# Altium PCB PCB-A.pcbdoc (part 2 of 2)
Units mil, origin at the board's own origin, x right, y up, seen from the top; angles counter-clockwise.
Board outline 6045 x 2702.2 mil, 4 copper layers (Top Layer, Inner1, Inner2, Bottom Layer); 82 components, 118 nets, 419 pads, 214 vias.
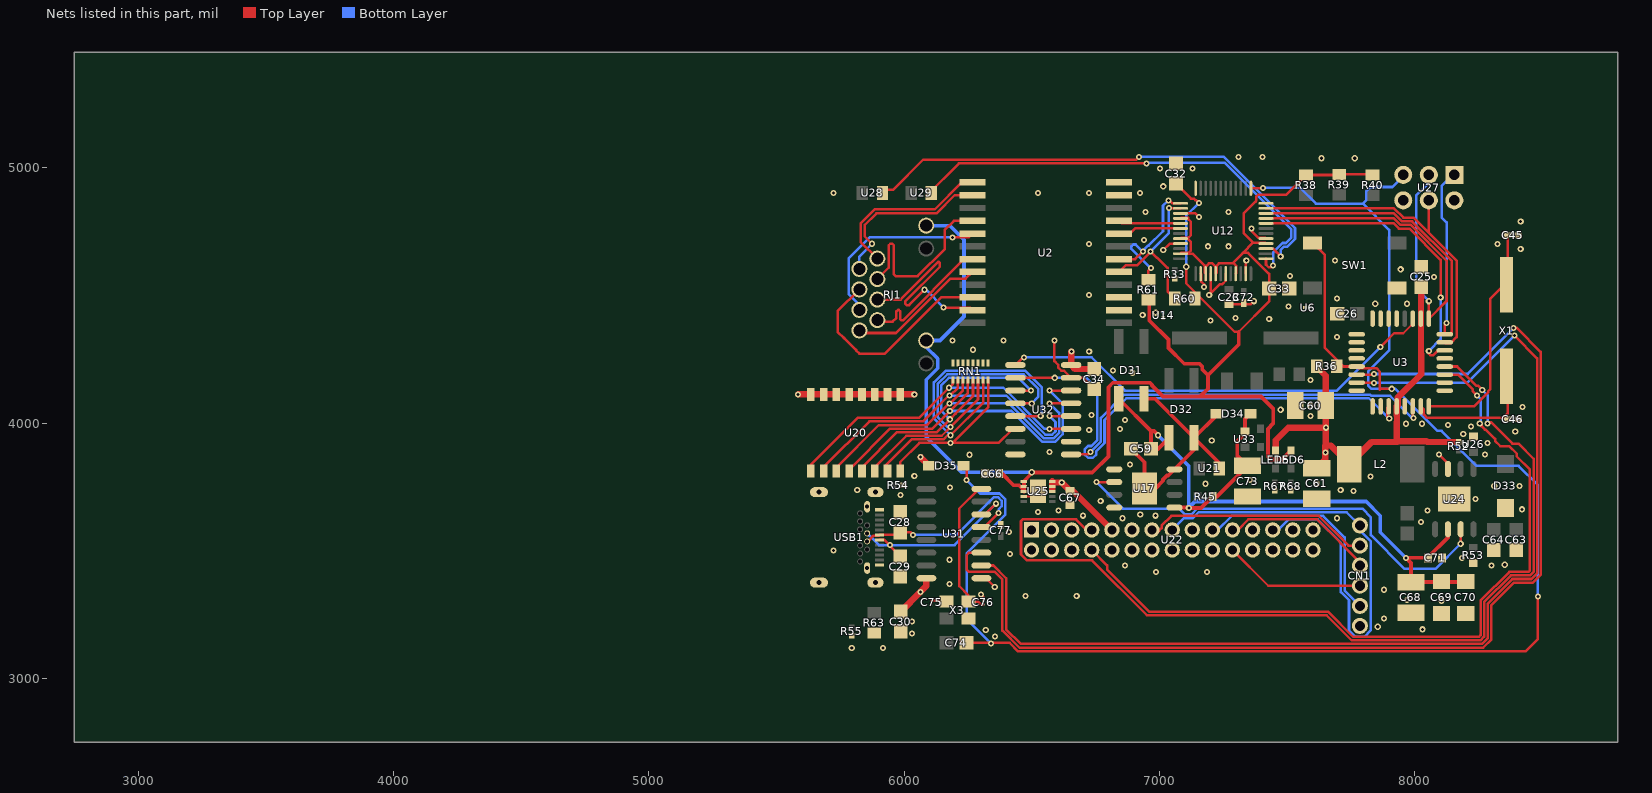
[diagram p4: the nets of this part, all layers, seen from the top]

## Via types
v1: diameter 24, hole 12, Top Layer to Bottom Layer, 173 vias
v2: diameter 24.02, hole 12.01, Top Layer to Bottom Layer, 41 vias

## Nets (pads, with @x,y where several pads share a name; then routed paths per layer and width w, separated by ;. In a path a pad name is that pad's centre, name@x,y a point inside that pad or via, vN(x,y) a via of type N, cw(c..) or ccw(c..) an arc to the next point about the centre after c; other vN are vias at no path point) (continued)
$9N13153: C76.2 U31.8 X3.3 | length 560.3
  Top Layer w10: U31.8@6302.7,3742.2 6293.44,3742.2 6216,3664.77 6216,3361.41 6252.15,3325.25 X3.3@6252.15,3300.65 6290.22,3300.65 6301.11,3289.76 6309.77,3289.76 C76.2@6310,3289.54
+5V: C25.1 C30.1 C34.2 C60.2 C61.2 C67.2 D35.1 L2.2 LED5.2 R36.1 R52.2 U3.4 U3.18 U20.9 U20.10 U20.11 U20.12 U20.13 U20.14 U20.15 U20.16 U22.9 U25.8 U25.9 U25.10 U27.2 U31.16 U32.16 | length 3087.4
  Top Layer w25: v1(5585,4112.2) U20.16@5635,4112.2 U20.15@5685,4112.2 U20.14@5735,4112.2 U20.13@5785,4112.2 U20.12@5835,4112.2 U20.11@5885,4112.2 U20.10@5935,4112.2 U20.9@5985,4112.2 v1(6040,4112.2) ; C30.1@5987.65,3261.99 v1(6064.48,3338.82) 6087.3,3361.64 U31.16@6087.3,3392.2 ; v1(6065,3867.2) 6065,3865.27 D35.1@6098.07,3832.2 ; 6580.57,3742.2 U25.9@6580.57,3751.88 U25.10@6580.57,3771.57 ; U25.10@6585,3767.2 v1(6617.56,3767.2) C67.2@6650,3734.76 6660.59,3734.76 U22.9@6813.78,3581.57 ; v1(6655,4280.2) 6655,4228.18 U32.16@6654.02,4227.2 6669.65,4211.57 C34.2@6745,4211.57 ; LED5.2@7455,3892.63 7455,3932.2 7504.62,3981.82 v1(7652.09,3981.82) ; R36.1@7615.63,4222.2 7652.09,4185.75 C60.2@7652.09,4068.58 v1(7652.09,3981.82) ; C61.2@7616.27,3823.32 7650,3857.05 v1(7650,3884.94) 7650,3912.2 ; C25.1@8025,4532.83 8025,4490.35 8024.49,4489.84 8024.49,4269.57 8025,4269.06 8025,4191.77 7933.39,4100.16 7933.39,4069.34 U3.4@7929.25,4065.2 7929.25,4031.1 7930.51,4029.84 7930.51,4004.57 7929.25,4003.31 7929.25,3927.96 7931.6,3925.62 ; R52.2@8172.16,3925.62 8049.31,3925.62 8045.83,3929.09 7935.07,3929.09 7931.6,3925.62 ; 7650,3912.2 7671.28,3912.2 L2.2@7744.15,3839.33 7830.43,3925.62 7931.6,3925.62 ; 7650,3912.2 7652.09,3914.29 v1(7652.09,3981.82)
+33V: C32.1 C33.1 C66.2 LED6.2 R38.2 R39.2 R40.2 R60.2 R61.2 RJ1.9 RJ1.11 U12.4 U12.8 U12.11 U12.15 U12.17 U12.21 U12.28 U25.1 U25.2 U25.3 | length 6746.3
  Top Layer w10: C32.1@7065,4937.83 7123.56,4879.28 7134.72,4879.28 7141.79,4872.2 7145,4872.2 v2(7155,4862.2) ; U12.8@7082.68,4722.67 7086.07,4726.07 7113.64,4726.07 ; U12.4@7082.68,4801.41 7086.07,4804.81 7113.64,4804.81 7113.64,4798.03 7123.19,4788.49 7123.19,4735.61 7113.64,4726.07 ; v2(7105,4612.2) 7105,4547.2 7294.68,4357.52 7310.61,4357.52 7429.88,4476.79 C33.1@7429.88,4526.84 7429.88,4584.09 7347.79,4666.18 7327.07,4666.18 ; U12.15@7181.1,4584.88 7177.72,4588.27 7177.72,4615.85 ; U12.21@7299.21,4584.88 7300.83,4586.5 7300.83,4615.85 7291.28,4625.4 7286.28,4625.4 ; 7376.79,4867.21 7330,4820.42 7330,4743.64 7367.26,4706.38 ; 7380,4870.42 7380,4887.2 7387.07,4894.28 7497.07,4894.28 R38.2@7574.25,4971.46 7702.14,4971.46 R39.2@7704.25,4973.56 7833.02,4973.56 R40.2@7835,4971.57 ; U12.28@7417.32,4702.99 7413.94,4706.38 7367.26,4706.38 ; 7113.64,4726.07 7113.64,4719.29 7123.19,4709.75 7123.19,4676.55 7113.64,4667.01 7086.06,4667.01 U12.11@7082.68,4663.62 7129.94,4663.62 7177.72,4615.85 ; 7177.72,4615.85 7184.49,4615.85 7194.04,4625.4 7207.54,4625.4 7220.47,4612.47 U12.17@7220.47,4584.88 7223.86,4588.28 7223.86,4615.85 7233.41,4625.4 7286.28,4625.4 ; 7286.28,4625.4 7327.07,4666.18 ; 7327.07,4666.18 7367.26,4706.38
  Top Layer w15: C66.2@6372.56,3802.2 6383.22,3802.2 6429.11,3756.31 6450.32,3756.31 U25.3@6469.43,3737.2 ; U25.3@6469.43,3732.2 U25.3@6469.43,3737.2 ; R61.2@6956.59,4482.39 6960,4478.99 6960,4402.2 7035.17,4327.03 7035.17,4294.36 7097.33,4232.2 7156.58,4232.2 7167.49,4221.29 7167.49,4209.71 7190,4187.2 ; 7310.61,4357.52 7310.61,4307.81 7190,4187.2 ; LED6.2@7515,3892.63 7479.57,3857.2 7435.61,3857.2 7425,3867.81 7425,3977.2 7445.5,3997.7 7445.5,4056.7 7398.24,4103.97 7159.59,4103.97 ; U25.3@6469.43,3737.2 U25.2@6469.43,3751.88 U25.1@6469.43,3771.57 6480.4,3782.54 6480.4,3784.06 6502.05,3805.7 6736.79,3805.7 6800,3868.92 6800,4140.43 6817.27,4157.71 6962.73,4157.71 6970.63,4149.8 6970.63,4147.47 7014.14,4103.97 7159.59,4103.97 ; 7159.59,4103.97 7190,4134.38 7190,4187.2
  Bottom Layer w10: v2(7105,4612.2) 7105,4812.2 v2(7155,4862.2)
  Bottom Layer w15: RJ1.9@6086.77,4772.88 6180,4772.87 6235,4717.87 6235,4417.2 6141.07,4323.27 RJ1.11@6086.77,4323.27 6086.76,4297.14 6131.76,4252.14 6131.76,4214.87 6086.76,4169.87 6086.76,3945.44 6225,3807.2 v1(6500,3807.2)
A0: U3.23
A1: U3.24
A2: U3.25
A3: U3.26
A4: U3.27
A5: U3.28
A6: U3.19 U32.1 | length 1751.2
  Top Layer w10: U32.1@6435.98,4227.2 6465.98,4257.2 v1(6470,4257.2) ; v1(7865,4297.2) 7919.54,4351.74 7954.99,4351.74 7992.24,4388.99 U3.19@7992.24,4409.2
  Bottom Layer w10: v1(6470,4257.2) 6735,4257.2 6865,4127.2 7695,4127.2 v1(7865,4297.2)
A7: U3.22
ACTLED: U12.27 U28.1 | length 1998.2
  Top Layer w10: U28.1@5915.5,4913.35 5956.35,4913.35 6074.2,5031.2 6909,5031.2 v2(6920,5042.2) ; U12.27@7417.32,4683.3 7444.93,4683.3 7457.85,4670.38 7457.85,4669.36 v1(7475,4652.2)
  Bottom Layer w10: v2(6920,5042.2) 6921.07,5043.27 7251.07,5043.27 7531.01,4763.33 7531.01,4721.08 7501.13,4691.2 7488.43,4691.2 7475,4677.76 v1(7475,4652.2)
AGND: C23.1 C25.2 C26.1 C28.1 C29.1 C30.2 C32.2 C33.2 C34.1 C45.2 C46.1 C60.1 C61.1 C63.1 C64.1 C66.1 C67.1 C68.1 C69.1 C70.1 C71.1 C72.1 C73.1 C75.1 C76.1 C77.1 CN1.1 D33.2 R33.1 R53.1 R54.2 R55.2 R63.2 R67.1 R68.1 RN1.1 RN1.2 RN1.3 RN1.4 RN1.5 RN1.6 RN1.7 RN1.8 SW1.1 U3.5 U3.21 U6.1 U12.3 U12.9 U12.14 U12.16 U12.19 U12.23 U12.29 U12.48 U14.1 U17.5 U17.8 U22.10 U22.16 U22.26 U24.7 U24.9 U25.4 U25.11 U26.1 U27.6 U31.1 U32.8 U32.10 U32.15 USB1.25 USB1.26 USB1.27 USB1.28 USB1.A1 USB1.A12 USB1.B1 USB1.B12 X3.2 X3.4 | length 1217.2
  Top Layer w10: C75.1@6107.61,3304.9 6161.29,3304.9 X3.4@6165.53,3300.65 ; v1(6301.73,3327.95) 6310,3319.68 C76.1@6310,3304.9 ; U31.1@6302.7,3392.2 6320,3392.2 v1(6355,3357.2) ; U25.4@6469.43,3712.51 6505.31,3712.51 U25.11@6525,3732.2 ; v1(6588.95,4322.85) 6588.95,4242.27 6602.9,4228.32 6602.9,4217.97 6615.96,4204.91 6626.32,4204.91 U32.15@6654.02,4177.2 6700.63,4177.2 C34.1@6745,4132.83 ; v1(7015,4677.2) 7040.79,4702.99 U12.9@7082.68,4702.99 ; U12.3@7082.68,4821.1 7141.1,4821.1 v1(7155,4807.2) ; U12.14@7161.42,4584.88 7163.72,4582.59 7163.72,4554.98 7175,4543.7 v1(7175,4532.2) ; v1(7195,4502.2) v1@7200.79,4507.99 ; U12.16@7200.79,4584.88 v1@7200.79,4507.99 ; U12.19@7259.84,4584.88 7259.84,4557.28 7246.92,4544.36 7237.15,4544.36 v1@7200.79,4507.99 ; C23.1@7272.81,4465.49 7358.29,4465.49 v1(7370,4477.2) ; U12.23@7338.58,4584.88 7338.58,4635.17 v1(7340.31,4636.9) ; v1(7360,4762.2) 7360,4752.4 7386.35,4726.05 7413.94,4726.05 U12.29@7417.32,4722.67 ; v1(8095,3877.2) 8130,3842.2 U24.7@8130,3820.32
  other v1: 5795,3118.65 5916.78,3118.65 6355.78,3163.95 6031.03,3175.13 6319.72,3190.12 8030,3192.2 7855,3202.2 6031.03,3222.62 7879.27,3234.02 8105,3303.95 7970,3307.2 6476.06,3323.12 6676.06,3323.12 7880,3347.2 6178.19,3369.32 6986.5,3416.67 7186.5,3416.67 6865,3442.2 8300,3442.2 8352.48,3445.16 6178.19,3464.68 8185,3472.2 6415,3487.2 5724.1,3501.3 6410.08,3573.11 8025,3612.2 6855,3627.2 7695,3627.2 6700,3637.2 6985,3637.2 6925,3642.2 6525,3652.2 6605,3657.2 8050,3657.2 8420,3662.2 6770,3694.2 8238.47,3702.21 5985.4,3717.83 7759.95,3734.24 5816.55,3737.21 7710,3737.2 6180,3747.2 8311.13,3753.58 8410.16,3753.58 7180,3762.2 7616.27,3763.58 7355,3777.2 7826.62,3791.3 6040,3792.2 6884.7,3837.38 6256.45,3875.79 8275,3877.2 6570,3887.2 8285,3922.2 7205,3932.2 8190,3957.2 8393.57,3967.2 6725,3972.2 6845,3977.2 8220,3987.2 8130,3992.2 7965,3997.2 8028.57,3997.2 6865,4012.2 7592.35,4027.55 6734,4030.97 7475,4052.2 8421.36,4063.57 7592.35,4068.58 7592.35,4168.04 6894.15,4197.24 6818.76,4205.97 6725,4280.2 6270,4287.2 6188.95,4322.85 6388.95,4322.85 7695,4337.2 7200,4402.2 7430,4407.2 7298.56,4411.36 6934.5,4423.64 6985.5,4432.2 7505,4457.2 7845.37,4467.2 7970,4467.2 7695.91,4487.2 6724.1,4501.3 8075,4572.2 7511.67,4576.61 7945,4602.2 7687.72,4637.02 8415,4682.2 7190,4692.2 7270,4692.2 6724.1,4701.3 8324.1,4701.3 6940,4717.2 8415,4789.94 6945,4827.2 7270,4827.2 5724.1,4901.3 6524.1,4901.3 6724.1,4901.3 6924.1,4901.3 7015,4927.2 7002.1,4997.2 7130,4997.2 7635,5037.2 7765,5037.2 7310,5042.2 7404.09,5042.2
CAN_H: U22.1
CAN_H2: U22.3
CAN_L: U22.2
CAN_L2: U22.4
CDB: U17.6 U24.3 | length 1793
  Top Layer w10: v1(6753.76,3768.44) 6822.59,3768.44 U17.6@6823.09,3768.93 ; v1(8180,3527.2) U24.3@8180,3584.1
  Bottom Layer w10: v1(6753.76,3768.44) 6857,3665.2 7077,3665.2 7100,3642.2 7125.73,3642.2 7148.1,3664.57 7794.58,3664.57 7828.25,3630.9 7828.25,3561.43 7960.47,3429.2 8082,3429.2 v1(8180,3527.2)
D0: U3.30 U31.3 | length 4515.3
  Top Layer w10: U31.3@6302.7,3492.2 6255,3492.2 6245,3482.2 6245,3427.2 6255,3417.2 6355.2,3417.2 6385,3387.41 6385,3187.2 6452.2,3120 8267.8,3120 8300,3152.2 8300,3287.2 8388,3375.2 8463,3375.2 8493.2,3405.4 8493.2,4279 8400,4372.2 v2(8386.96,4372.2) ; U3.30@7772.5,4189.96 7837.76,4189.96 v2(7840,4192.2)
  Bottom Layer w10: v2(7840,4192.2) 8206.96,4192.2 v2(8386.96,4372.2)
D1: U3.31 U31.2 | length 4277.2
  Top Layer w10: U31.2@6302.7,3442.2 6350,3442.2 6400,3392.2 6400,3192 6457.15,3134.86 8262.85,3134.86 8286,3158 8286,3293 8382.2,3389.2 8457.2,3389.2 8479.2,3411.2 8479.2,4253 v2(8390,4342.2) ; U3.31@7772.5,4158.46 7773.76,4157.2 v2(7840,4157.2)
  Bottom Layer w10: v2(7840,4157.2) 8205,4157.2 v2(8390,4342.2)
D2: U3.32
D3: U3.1
D4: U3.2
D5: U3.9
D6: U3.10
D7: U3.11 U22.8 | length 3014.5
  Top Layer w10: U22.8@6735.04,3502.83 6795.04,3442.83 6795.04,3426.21 6960.04,3261.2 7660.8,3261.2 7759.15,3162.86 8251.26,3162.86 8258,3169.6 8258,3304.6 8370.6,3417.2 8445.6,3417.2 8451.2,3422.8 8451.2,3817.72 8399.46,3869.46 8399.46,3879.89 8369.73,3909.62 8334.92,3909.62 8314.44,3930.09 8314.44,3937.62 8277.44,3974.62 8274.92,3974.62 8261.44,3988.09 8261.44,3990.62 v1(8254.44,3997.62) ; U3.11@8117.5,4189.96 8168.96,4189.96 8227.66,4131.26 8227.66,4124.19 v2(8243.22,4108.62)
  Bottom Layer w10: v2(8243.22,4108.62) 8258.79,4093.06 8258.79,4001.96 v1(8254.44,3997.62)
D8: U3.12 U22.7 | length 3775.6
  Top Layer w10: U22.7@6735.04,3581.57 6714.28,3581.57 6673.28,3622.57 6464.26,3622.57 6457.82,3616.13 6457.82,3485.85 6481.84,3461.83 6736.13,3461.83 6950.76,3247.2 7655,3247.2 7753.35,3148.86 8257.06,3148.86 8272,3163.8 8272,3298.8 8376.4,3403.2 8451.4,3403.2 8465.2,3417 8465.2,3860.29 8406.21,3919.28 8382.93,3919.28 8300,4002.2 8289.03,4002.2 v1(8284.44,3997.62) ; U3.12@8117.5,4221.46 8165.75,4221.46 8241.81,4145.4 8248.88,4145.4 v2(8264.44,4129.84)
  Bottom Layer w10: v2(8264.44,4129.84) 8285.86,4108.42 8285.86,3999.03 v1(8284.44,3997.62)
D9: U3.13
DIR: U22.11
DN1: C29.2 U31.6 USB1.A7 USB1.B7 | length 773.8
  Top Layer w10: USB1.A7@5903.31,3542.36 5922.8,3542.36 v1@5945,3520.16 ; v1@5945,3518.71 5944.53,3518.25 C29.2@5985.4,3477.38 ; U31.6@6302.7,3642.2 6317.47,3642.2 v1(6359.45,3684.18)
  Bottom Layer w10: USB1.B7@5855.67,3567.96 5864.35,3559.27 5865.11,3559.27 5878.47,3545.9 5878.47,3545.14 5901.41,3522.2 v1(5945,3522.2) 6197.47,3522.2 v1(6359.45,3684.18)
DP1: C28.2 U31.5 USB1.A6 USB1.B6 | length 755.9
  Top Layer w10: USB1.B6@5855.67,3536.46 5858.22,3536.45 5881.04,3559.27 5900.54,3559.27 USB1.A6@5903.31,3562.04 5975.55,3562.04 C28.2@5985.4,3571.9 6025.31,3571.9 v1(6035,3562.2) ; U31.5@6302.7,3592.2 6315,3592.2 v1(6370,3647.2)
  Bottom Layer w10: v1(6035,3562.2) 6205,3562.2 6352.93,3710.13 6367.07,3710.13 6382.45,3694.75 6382.45,3674.66 6370,3662.2 v1(6370,3647.2)
ENCO_A: U22.17
ENCO_B: U22.18
ENCO_Z: U22.20
ETH1A: U2.2
ETH1B: U2.3
ETH2A: R60.1 U2.5 U12.2 | length 628.5
  Top Layer w10: U2.5@6842.4,4592.2 6868.74,4618.54 6913.85,4618.54 6965,4669.69 v2(6965,4672.2) 6990,4647.2 6992.24,4647.2 7032.07,4607.37 7032.07,4515.76 R60.1@7060.63,4487.2 ; v2(7037.07,4841.74) 7081.73,4841.74 U12.2@7082.68,4840.78
  Bottom Layer w10: v2(6965,4672.2) 7037.07,4744.28 v2(7037.07,4841.74)
ETH2B: R61.1 U2.6 U12.1 | length 627.5
  Top Layer w10: U2.6@6842.4,4642.2 6905,4642.2 v2(6935,4672.2) ; R61.1@6956.59,4561.13 6956.59,4597.2 v1(6966.59,4607.2) ; v2(7035,4872.2) 7037.93,4869.28 7042.07,4869.28 7050.87,4860.47 U12.1@7082.68,4860.47
  Bottom Layer w10: v1(6966.59,4607.2) 6965,4607.2 6890,4682.2 6890,4692.2 6897.07,4699.28 6907.07,4699.28 6934.14,4672.2 v2(6935,4672.2) 6941.99,4679.2 6941.99,4681.73 6955.47,4695.21 6958.01,4695.21 7014.06,4751.27 7014.06,4851.27 v2(7035,4872.2)
ETH3A: U2.8 U12.6 | length 248.6
  Top Layer w10: U2.8@6842.4,4742.2 6885,4742.2 6905,4762.2 7082.52,4762.2 U12.6@7082.68,4762.04
ETH3B: U2.9 U12.5 | length 244.6
  Top Layer w10: U2.9@6842.4,4792.2 6852.87,4781.73 U12.5@7082.68,4781.73
ETH4A: U2.11
ETH4B: U2.12
HALL_A: CN1.4 U22.21 | length 604.9
  Top Layer w10: U22.21@7286.22,3581.57 7306.98,3581.57 7347.98,3622.57 7618.16,3622.57 7792.08,3448.66 CN1.4@7785,3441.57
HALL_B: CN1.3 U22.22 | length 556.8
  Top Layer w10: U22.22@7286.22,3502.83 7426.22,3362.83 CN1.3@7785,3362.83
HALL_C: CN1.2 U22.19 | length 868.2
  Bottom Layer w10: U22.19@7207.48,3581.57 7228.24,3581.57 7283.24,3636.57 7640.63,3636.57 7725,3552.2 7725,3344.09 CN1.2@7785,3284.09
IP0: RN1.9 U20.1 U32.11 | length 1272.8
  Top Layer w10: U20.1@5635,3812.2 5635,3837.2 5818,4020.2 6057.92,4020.2 v1@6175.92,4138.2 ; v1(6176,4138.2) 6191.1,4153.3 RN1.9@6191.1,4169.41 ; v1(6570,3977.2) U32.11@6654.02,3977.2
  Bottom Layer w10: v1(6176,4138.2) 6389,4138.2 6550,3977.2 v1(6570,3977.2)
IP1: RN1.10 U20.2 U32.12 | length 1338.5
  Top Layer w10: U20.2@5685,3812.2 5685,3827.2 5864,4006.2 6073.92,4006.2 6174.97,4107.26 v1(6177.5,4107.26) 6180.05,4107.26 6210.79,4137.99 RN1.10@6210.79,4169.41 ; v1(6570,4027.2) U32.12@6654.02,4027.2
  Bottom Layer w10: v1(6177.5,4107.26) 6400.15,4107.26 6553.2,3954.2 6579.53,3954.2 6593,3967.68 6593,4004.2 v1(6570,4027.2)
IP2: RN1.11 U20.3 U32.13 | length 1386.1
  Top Layer w10: U20.3@5735,3812.2 5735,3826.35 5900.86,3992.2 6090,3992.2 6175.05,4077.26 v1(6177.5,4077.26) 6180.11,4077.26 6230.47,4127.62 RN1.11@6230.47,4169.41 ; v1(6570,4077.2) U32.13@6654.02,4077.2
  Bottom Layer w10: v1(6177.5,4077.26) 6410.35,4077.26 6547.4,3940.2 6585.33,3940.2 6607,3961.88 6607,4040.2 v1(6570,4077.2)
IP3: RN1.12 U20.4 U32.14 | length 1429
  Top Layer w10: U20.4@5785,3812.2 5786.82,3812.2 5790,3815.39 5790,3822.72 5945.48,3978.2 6110.49,3978.2 6156.01,4023.73 6156.01,4024.26 v1(6179.01,4047.26) 6180.11,4047.26 6250.16,4117.31 RN1.12@6250.16,4169.41 ; v1(6570,4127.2) U32.14@6654.02,4127.2
  Bottom Layer w10: v1(6179.01,4047.26) 6420.55,4047.26 6541.6,3926.2 6591.12,3926.2 6621,3956.08 6621,4076.2 v1(6570,4127.2)
IP4: RN1.13 U20.5 U32.3 | length 1222.5
  Top Layer w10: U20.5@5835,3812.2 5835,3826.35 5972.86,3964.2 6128.49,3964.2 v1(6179.01,4014.73) 6188.01,4023.73 6188.54,4023.73 6202.01,4037.2 6202.01,4037.73 6269.84,4105.56 RN1.13@6269.84,4169.41 ; U32.3@6435.98,4127.2 v1(6497.47,4127.2)
  Bottom Layer w10: v1(6179.01,4014.73) 6145,4048.74 6145,4147.2 6175,4177.2 6447.47,4177.2 v1(6497.47,4127.2)
IP5: RN1.14 U20.6 U32.4 | length 1367.9
  Top Layer w10: U20.6@5885,3812.2 5885,3826.35 6008.86,3950.2 6147.47,3950.2 v1(6182,3984.73) 6289.53,4092.26 RN1.14@6289.53,4169.41 ; U32.4@6435.98,4077.2 v1(6500,4077.2)
  Bottom Layer w10: v1(6182,3984.73) 6169.27,3984.73 6131,4023 6131,4153 6169.2,4191.2 6468.53,4191.2 6525,4134.73 6525,4102.2 v1(6500,4077.2)
IP6: RN1.15 U20.7 U32.5 | length 1513.7
  Top Layer w10: U20.7@5935,3812.2 5927.5,3819.7 5927.5,3833.85 6029.86,3936.2 6154.27,3936.2 6170.27,3952.2 v1(6182,3952.2) 6309.21,4079.41 RN1.15@6309.21,4169.41 ; U32.5@6435.98,4027.2 v1(6535,4027.2)
  Bottom Layer w10: v1(6182,3952.2) 6117,4017.2 6117,4158.8 6163.4,4205.2 6474.33,4205.2 6539,4140.53 6539,4031.2 v1(6535,4027.2)
IP7: RN1.16 U20.8 U32.6 | length 844.6
  Top Layer w10: U20.8@5985,3812.2 5985,3847.2 6060,3922.2 v1(6182,3922.2) v1@6190,3922.2 ; RN1.16@6328.9,4169.41 6328.9,4061.1 v1@6190,3922.2 ; U32.6@6435.98,3977.2 6425.63,3977.2 6370.63,3922.2 v1@6190,3922.2
LINKLED: U12.25 U29.1 | length 1834
  Top Layer w10: U29.1@6089.37,4892.2 6214.37,5017.2 v2(6950,5017.2) ; U12.25@7417.32,4643.93 7417.32,4620.74 7427.93,4610.13 7437.93,4610.13 v2(7445,4617.2)
  Bottom Layer w10: v2(6950,5017.2) 6952.01,5015.2 6952.01,5010.2 6962.01,5020.2 7254.34,5020.2 7517.01,4757.53 7517.01,4726.88 7495.33,4705.2 7482.63,4705.2 7445,4667.56 v2(7445,4617.2)
MISO: U3.16 U12.34 U27.1 | length 1768
  Top Layer w10: U12.34@7417.32,4821.1 7918.42,4821.1 7949.33,4790.2 7990,4790.2 8144.37,4635.83 8144.37,4356.57 8135.24,4347.44 U3.16@8117.5,4347.44 8117.5,4384.7 v2(8125,4392.2)
  Bottom Layer w10: v2(8125,4392.2) 8125,4785.67 8105.55,4805.12 8105.55,4927.76 U27.1@8150,4972.2
MOSI: U3.15 U12.35 U27.4 | length 1318.6
  Top Layer w10: U12.35@7417.32,4840.78 7918.56,4840.78 7955.13,4804.21 7995.81,4804.21 8055,4745.02 ; U27.4@8050,4872.2 8055,4867.2 8055,4745.02 ; U3.15@8117.5,4315.94 8121.24,4312.2 8140,4312.2 8164.05,4336.25 8164.05,4635.97 8055,4745.02
OCTCLK: U3.3 U32.2 | length 2065.9
  Top Layer w10: U32.2@6435.98,4177.2 v1(6590,4177.2) ; U3.3@7897.76,4065.2 7892.07,4059.52 7892.07,4025.13 v2(7900,4017.2)
  Bottom Layer w10: v1(6590,4177.2) 6715,4177.2 6757,4135.2 6757,3934 6733.2,3910.2 6720.47,3910.2 6707,3896.73 6707,3877.68 6720.47,3864.2 6739.53,3864.2 6753,3877.68 6753,3890.41 6785,3922.41 6785,4012 6870.2,4097.2 7820,4097.2 v2(7900,4017.2)
OCTR: U3.6 U32.9 | length 1575.8
  Top Layer w10: U32.9@6654.02,3877.2 6720,3877.2 v1(6730,3887.2) ; U3.6@7992.24,4065.2 7992.24,4022.95 v2(7995,4020.2)
  Bottom Layer w10: v1(6730,3887.2) 6771,3928.2 6771,4020.46 6861.75,4111.2 7825.8,4111.2 7830.78,4106.22 7903.98,4106.22 7990,4020.2 v2(7995,4020.2)
ODRV5V: CN1.6 U22.15 U22.25 | length 1998.9
  Bottom Layer w10: U22.15@7050,3581.57 7096.63,3628.2 7131.53,3628.2 7153.9,3650.57 7733.48,3650.57 CN1.6@7785,3599.05 7783.96,3598.02 7783.96,3581.45 7827.5,3537.92 7827.5,3187.75 7802.6,3162.86 7767.4,3162.86 7742.5,3187.75 7742.5,3306.79 7711,3338.3 7711,3531.2 7619.63,3622.57 7505.46,3622.57 7464.46,3581.57 U22.25@7443.7,3581.57
ODRV12IN: U22.5
ODRV33V: U22.6
ODRVSPI_CS: U22.30
ODRVSPI_MISO: U22.28
ODRVSPI_MOSI: U22.27
ODRVSPI_SCK: U22.29
POE+: C59.1 C68.2 C69.2 C70.2 C71.2 C73.2 D31.3 D32.3 D34.1 R45.2 U17.1 U24.2 U33.1 | length 2843.1
  Top Layer w15: D31.3@6840.78,4095.09 6967.62,3968.25 ; v1(6995,3952.2) 6978.95,3968.25 6967.62,3968.25 ; D32.3@7037.64,3942.36 6994.21,3898.93 C59.1@6967.62,3898.93 6967.62,3968.25 ; U17.1@7059.31,3668.93 7113.27,3668.93 v1(7115,3667.2) 7163.53,3667.2 R45.2@7208.53,3712.2 7225.26,3712.2 C73.2@7345,3831.94 7304.49,3872.45 7304.49,3928.37 7335,3958.88 U33.1@7335,3966.22 7335,4015.27 D34.1@7356.93,4037.2 ; U24.2@8130,3584.1 8130,3552.33 8050,3472.32 7965.12,3472.32 v1(7965,3472.2) 7985,3452.2 C68.2@7985,3376.94 8197.03,3376.94 C70.2@8200,3379.9
  Bottom Layer w15: v1(6995,3952.2) 7115,3832.2 v1(7115,3667.2) 7140,3692.2 7810,3692.2 7865,3637.2 7865,3572.2 v1(7965,3472.2)
POE-: C59.2 D31.4 D32.4 D34.2 U17.4 U17.9 U21.1 | length 1035.4
  Top Layer w15: C59.2@6888.88,3898.93 6941.2,3846.62 U17.9@6941.2,3743.93 6984.31,3743.93 7014.31,3773.94 7014.31,3779.42 7029.14,3794.24 7034.62,3794.24 U17.4@7059.31,3818.93 7136.08,3895.71 D32.4@7136.08,3942.36 ; D31.4@6939.22,4095.09 6983.35,4095.09 D32.4@7136.08,3942.36 ; D34.2@7229,4032.2 7225.92,4032.2 D32.4@7136.08,3942.36 ; U21.1@7234.37,3822.2 7234.37,3844.07 D32.4@7136.08,3942.36
RJ1A: RJ1.4 U2.23 | length 847
  Top Layer w10: RJ1.4@5895.04,4483.12 5985.91,4483.11 6134.82,4632.03 6140,4626.85 6140,4612.2 6005,4477.2 6005,4467.2 6010,4462.2 6020,4462.2 v2(6080,4522.2) ; v2(6155,4452.2) 6257.6,4452.2 U2.23@6267.6,4442.2
  Bottom Layer w10: v2(6080,4522.2) 6085,4522.2 v2(6155,4452.2)
RJ1B: RJ1.5 U2.22 | length 856
  Top Layer w10: RJ1.5@5824.96,4523.27 5740,4438.32 5740,4357.2 5764.13,4333.08 5765.52,4333.08 5812.32,4286.28 5812.32,4284.89 5825,4272.2 5925,4272.2 6145,4492.2 U2.22@6267.6,4492.2
RJ2A: RJ1.1 U2.20 | length 546
  Top Layer w10: RJ1.1@5824.96,4362.64 5834.95,4352.64 5968.05,4352.64 6181.27,4565.87 6241.26,4565.87 U2.20@6267.6,4592.2
RJ2B: RJ1.2 U2.19 | length 539.9
  Top Layer w10: RJ1.2@5895.04,4402.8 5900.63,4397.2 5955,4397.2 5970,4412.2 5970,4436.8 ; 5972.46,4439.26 5977.7,4444.5 5985,4437.2 5985,4407.2 5990,4402.2 5995,4402.2 6235,4642.2 U2.19@6267.6,4642.2
RJ3A: RJ1.3 U2.17 | length 744.8
  Top Layer w10: v2(6189.8,4727) 6252.4,4727 U2.17@6267.6,4742.2
  Bottom Layer w10: RJ1.3@5824.96,4442.96 5824.95,4463.2 5782.47,4505.68 5782.47,4644.68 5864.8,4727 v2(6189.8,4727)
RJ3B: RJ1.6 U2.16 | length 734.9
  Top Layer w10: RJ1.6@5895.04,4563.43 5940,4608.4 5940,4696.35 5945.86,4702.2 5954.14,4702.2 5960,4696.35 5960,4582.2 5967.07,4575.13 6052.93,4575.13 6160,4682.2 6160,4757.2 6195,4792.2 U2.16@6267.6,4792.2
RJ4A: RJ1.7 U2.14 | length 674.7
  Top Layer w10: v2(5875,4702.2) 5845.98,4731.22 5845.98,4775.58 5891.62,4821.22 6126.62,4821.22 6197.61,4892.2 U2.14@6267.6,4892.2
  Bottom Layer w10: RJ1.7@5824.96,4603.59 5824.95,4652.16 v2(5875,4702.2)
RJ4B: RJ1.8 U2.13 | length 669.3
  Top Layer w10: RJ1.8@5895.04,4643.75 5830,4708.78 5830,4782.2 5885,4837.2 6120,4837.2 6225,4942.2 U2.13@6267.6,4942.2
RS_485A: U22.23
RS_485B: U22.24
RST: C74.1 D35.2 R36.2 SW1.4 U3.29 U12.37 U27.5 | length 6893.8
  Top Layer w10: D35.2@6231.93,3832.2 6245,3819.13 v1(6245,3777.2) ; C74.1@6244.47,3139.54 6412.87,3139.54 6446.41,3106 8433.8,3106 8482.07,3154.28 v2(8482.07,3320.33) ; U12.37@7358.27,4919.52 7405,4919.52 v2(7406.18,4920.7) ; SW1.4@7599.65,4705.78 7648.04,4657.4 7648.04,4294.17 7720.75,4221.46 U3.29@7772.5,4221.46 7778.76,4215.2 7849.52,4215.2 7862.99,4201.73 7862.99,4130.96 7866.24,4134.21 v2(7910,4134.21)
  Bottom Layer w10: v1(6245,3777.2) 6298.07,3724.13 6372.87,3724.13 6396.45,3700.55 6396.45,3641.13 6245,3489.68 6245,3232.31 v1(6340.05,3137.26) ; v2(7406.18,4920.7) 7551.5,4920.7 7612.67,4859.53 7796.85,4859.53 ; U27.5@7950,4972.2 7950,4962.2 7912.32,4924.52 7826.84,4924.52 7810.32,4908 7810.32,4873 7796.85,4859.53 ; v2(8482.07,3320.33) 8482.07,3757.2 8407.07,3832.2 8242.52,3832.2 8105.52,3969.2 8089.16,3969.2 7924.14,4134.21 v2(7910,4134.21) 7830.48,4134.21 7817.01,4147.68 7817.01,4201.73 7900,4284.72 7900,4756.38 7796.85,4859.53
SCLK: U3.17 U12.33 U27.3 | length 1634.2
  Top Layer w10: U12.33@7417.32,4801.41 7918.29,4801.41 7943.92,4775.78 7984.6,4775.78 8124.68,4635.7 8124.68,4477.2 8119.02,4471.54 8119.02,4471.4 8056.82,4409.2 U3.17@8055.24,4409.2 8055,4409.44 v2(8055,4477.2)
  Bottom Layer w10: U27.3@8050,4972.2 8050,4935.06 8005.55,4890.62 8005.55,4526.65 v2(8055,4477.2)
STEP: U22.12
THERMISTOR+: CN1.5 U22.13 | length 897.4
  Top Layer w10: U22.13@6971.26,3581.57 6979.57,3573.27 6993.71,3573.27 7009,3588.56 7009,3598.56 7047.02,3636.57 7623.96,3636.57 7740.22,3520.31 CN1.5@7785,3520.31
THERMISTOR-: U22.14
W5500CS: U3.14 U12.32 | length 1203
  Top Layer w10: U12.32@7417.32,4781.73 7918.15,4781.73 7938.12,4761.76 7978.81,4761.76 8101.69,4638.89 v2(8101.69,4491.12) ; v2(8055,4282.2) 8055,4272.2 8062.07,4265.13 8072.07,4265.13 8091.39,4284.45 U3.14@8117.5,4284.45
  Bottom Layer w10: v2(8055,4282.2) 8101.69,4328.89 v2(8101.69,4491.12)
W5500INT: U12.36
XTAL1: C46.2 U3.7 X1.1 | length 536.9
  Top Layer w10: U3.7@8023.74,4065.2 8035.39,4053.55 8035.39,4033.36 8048.14,4020.62 8347.51,4020.62 8363.97,4037.08 X1.1@8363.97,4196.68
XTAL2: C45.1 U3.8 X1.2 | length 895.9
  Top Layer w10: U3.8@8055.24,4065.2 8232.32,4065.2 8287.43,4120.31 8287.43,4124.64 8295,4132.2 8295,4486.21 8363.97,4555.18 8363.97,4721.78 C45.1@8358.54,4727.2
pads on no net: SW1.2 SW1.3 U2.1 U2.4 U2.7 U2.10 U12.7 U12.12 U12.13 U12.18 U12.24 U12.26 U12.38 U12.39 U12.40 U12.41 U12.42 U12.46 U12.47 U25.5 U25.6 U25.7 U31.9 U31.10 U31.11 U31.12 U31.14 U31.15 U32.7 USB1.A2 USB1.A3 USB1.A4 USB1.A8 USB1.A9 USB1.A10 USB1.A11 USB1.B2 USB1.B3 USB1.B4 USB1.B8 USB1.B9 USB1.B10 USB1.B11
copper on no net: | length 51.8
  Top Layer w10: 7355,4584.88 7365,4574.88 v2(7365,4537.2)

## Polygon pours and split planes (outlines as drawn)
AGND on Top Layer (solid, remove dead copper, pour order 0): 5435,5132.2 8540,5132.2 8540,3032.2 5435,3032.2
AGND on Bottom Layer (solid, remove dead copper, pour order 2): 5385,5202.2 8545,5202.2 8545,3007.2 5385,3007.2

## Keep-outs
Board Outline Layer:
  circle w10: c8385,4962.2 r62.5
  circle w10: c8385,3212.2 r62.5
  circle w10: c5635,4962.2 r62.5
  circle w10: c5635,3212.2 r62.5
  lines w10: 5510,3087.2 8510,3087.2 8510,5087.2 5510,5087.2 5510,3087.2

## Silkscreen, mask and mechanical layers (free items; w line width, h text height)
Top Silkscreen Layer:
  text "ICSP" at 7890,5017.2 h60
  text "0  1  2" at 7574.25,5001.42 h60
  text "LNK SPD" at 7570,4792.2 h60
  text "GND" at 7900,4757.2 h60
  text "RST" at 7709.41,4746.91 h40
  text "Indicator 5V" at 7460,4042.2 h20 r270
  text "POE OK" at 7435,3987.2 h20 r270
  text "3.3V" at 7485,3957.2 h20 r270
  text "Octet Selection" at 6020,3907.2 h25
  text "1 2 4 8 16 32 64 128" at 6040,3872.2 h25
Bottom Silkscreen Layer:
  text "University Of Akron /  RMC Team /  2025" at 6188.27,4892.2 h40
  text "Lane Cline /  Eli Bukoski /  Garren Ward /  Jonathan Donley /  Alex Kinch /  Tatsuya Wachtl /  William Forcey /  Ethan Banning /  Seth McCord /  Logan Foster /  Zane Nold /  Liam Boich" at 6020,3752.2 h40
  text "O-Drive Rev Module" at 7655,3247.2 h120
  text "REV 2" at 7228.95,3120 h120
